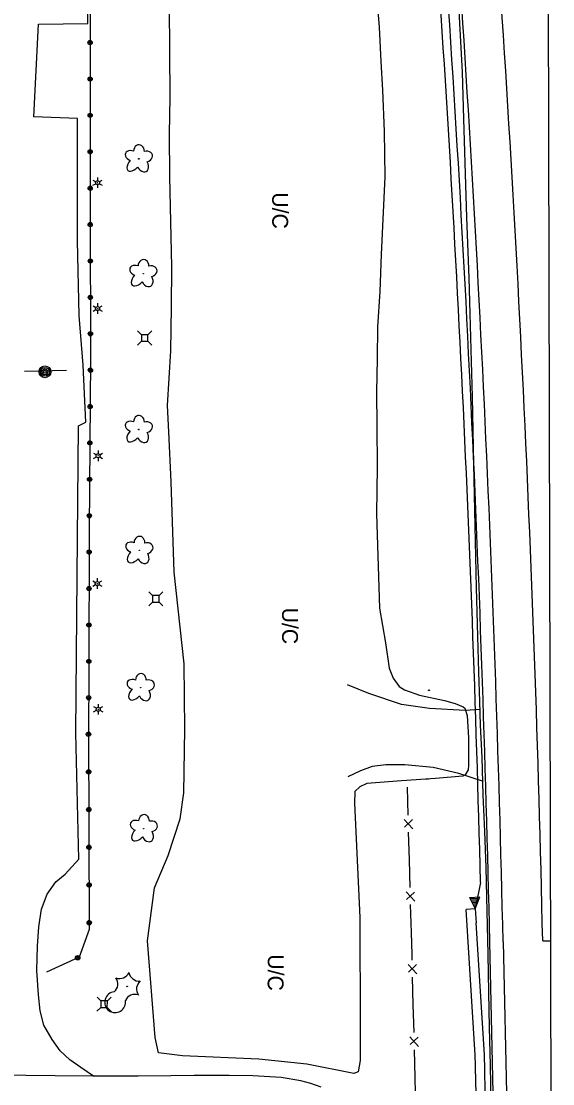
# Model space of a CAD drawing. Extents: x 588843 to 2552415, y 180129 to 269402.
# Drawn here: x 593754.5 to 593955.5, y 184000.1 to 184402 of the extents above; entities that cross this region are included whole.
import ezdxf

# ---------------------------------------------------------------- set-up
doc = ezdxf.new("R2010")
doc.units = 0
for name, color, linetype in [('Default', 7, 'Continuous'), ('E_AREA', 7, 'Continuous'), ('E_AREA_Text', 7, 'Continuous'), ('E_BMGRD_P', 7, 'Continuous'), ('E_DRN', 7, 'Continuous'), ('E_DWY', 7, 'Continuous'), ('E_FEN_P', 7, 'Continuous'), ('E_LAND_Vegetation', 7, 'Continuous'), ('E_LTG', 7, 'Continuous'), ('E_MISCPROP', 7, 'Continuous'), ('E_RDWY_Gravel', 7, 'Continuous'), ('E_SGN', 7, 'Continuous'), ('E_UTL_AG_Bold', 7, 'Continuous'), ('P_BMGRD', 7, 'Continuous'), ('P_RDWY_PavtEdge', 7, 'Continuous'), ('P_RDWY_ShldAgg', 7, 'Continuous'), ('P_RDWY_ShldPaved', 7, 'Continuous')]:
    doc.layers.add(name, color=color, linetype=linetype)

# ---------------------------------------------------------------- blocks, each defined once
blk = doc.blocks.new('CULV2')
at = {"layer": 'E_DRN'}
blk.add_arc((20, 15), 24.6, 216.8699, 323.1301, dxfattribs=at)
blk = doc.blocks.new('UCA')
at = {"layer": 'E_AREA_Text'}
blk.add_text('U/C', height=12, dxfattribs=at).set_placement((-15.33, -6))
blk = doc.blocks.new('DTRE')
at = {"layer": 'Default'}
blk.add_circle((-0.18, 0), 0.183, dxfattribs=at)
for centre, major_axis, ratio in [((-1.87, 5.32), (1.36, -4.98), 0.782863), ((-5.87, 0.15), (4.93, -0.12), 0.832022), ((4.06, 2.74), (-5.27, -2.93), 0.691916), ((-2.49, -5.24), (1.8, 4.86), 0.716896), ((3.54, -3.71), (-5.01, 4.58), 0.560249)]:
    blk.add_ellipse(centre, major_axis=major_axis, ratio=ratio, start_param=1.570796, end_param=4.712389, dxfattribs=at)
blk = doc.blocks.new('PED')
at = {"layer": 'Default'}
for p, q in [((-2.5, 2.5), (-5.33, 5.33)), ((2.5, 2.5), (5.33, 5.33)), ((-2.5, -2.5), (-5.33, -5.33)), ((2.5, -2.5), (5.33, -5.33))]:
    blk.add_line(p, q, dxfattribs=at)
blk.add_lwpolyline([(-2.5, -2.5), (2.5, -2.5), (2.5, 2.5), (-2.5, 2.5)], close=True, dxfattribs=at)
blk = doc.blocks.new('CTRE')
at = {"layer": 'Default'}
blk.add_circle((0, 0), 0.223, dxfattribs=at)
for centre, start, end in [((-11.97, 8.96), 280.2067, 5.97162), ((1.81, 14.92), 220.21132, 305.97623), ((13.83, 5.89), 160.21133, 245.97624), ((-13.83, -5.9), 340.21132, 65.97623), ((-1.81, -14.93), 40.21133, 125.97624), ((12.03, -9.04), 185.92721, 100.25111)]:
    blk.add_arc(centre, 7.87, start, end, dxfattribs=at)
blk = doc.blocks.new('LPOL')
at = {"layer": 'Default'}
for p, q in [((-4, 0), (-1.5, 0)), ((-0.75, 1.3), (-2, 3.46)), ((0.75, 1.3), (2, 3.46)), ((1.5, 0), (4, 0)), ((-2, -3.46), (-0.75, -1.3)), ((2, -3.46), (0.75, -1.3))]:
    blk.add_line(p, q, dxfattribs=at)
for radius in [1.5, 1.5, 1.5, 0.125]:
    blk.add_circle((0, 0), radius, dxfattribs=at)
blk = doc.blocks.new('UCA_1')
at = {"layer": 'E_AREA_Text'}
blk.add_text('U/C', height=12, dxfattribs=at).set_placement((-15.33, -6))
blk = doc.blocks.new('POLE')
at = {"layer": 'Default'}
for radius in [4.46, 3.35, 2.23, 1.12]:
    blk.add_circle((0, 0), radius, dxfattribs=at)

msp = doc.modelspace()

# ---------------------------------------------------------------- linework, layer by layer
at = {"layer": 'E_AREA'}
for points in [[(593816.37, 184134.26), (593816.12, 184158.88), (593812.36, 184193.55), (593811.23, 184227.73), (593810.27, 184246.66), (593809.76, 184256.58), (593811.11, 184277.31), (593811.33, 184293.82), (593811.47, 184309.05), (593810.7, 184343.1), (593810.61, 184359.45), (593810.77, 184373.26), (593810.42, 184425.33)], [(593888.88, 184412.4), (593889.82, 184399.75), (593890.51, 184386.73), (593891.1, 184375.95), (593891.82, 184360.27), (593892, 184343.2), (593890.62, 184313.77), (593890.06, 184299.74), (593889.19, 184286.34), (593889.06, 184274.26), (593888.92, 184261.75), (593889.02, 184248.78), (593889.13, 184233.47), (593888.92, 184215.64), (593889.95, 184179.98), (593892.25, 184166.85), (593893.62, 184157.27), (593895.13, 184153.44), (593897.45, 184150.32), (593899.45, 184149.09), (593905.12, 184147.01), (593914.61, 184145.08), (593918.59, 184143.95), (593921.64, 184142.7), (593922.29, 184142.14), (593923.19, 184139.4), (593923.62, 184130.94)], [(593923.62, 184130.94), (593923.67, 184120.53), (593923.5, 184118.86), (593922.4, 184116.96), (593921.49, 184116.45), (593911.2, 184115.49), (593898.27, 184114.64), (593885.21, 184113.67), (593882.5, 184112.39), (593880.69, 184110.63), (593880.51, 184106.27), (593882.58, 184062.91), (593882.69, 184021.58), (593882.64, 184008.81), (593881.91, 184004.53), (593880.33, 184003.89), (593862.55, 184007.45), (593844.37, 184009.43), (593815.43, 184010.68), (593806.44, 184011.82), (593805.18, 184017.62), (593802.24, 184054.1), (593804.84, 184074.23), (593810.11, 184086.4), (593814.56, 184100.27), (593816.02, 184110.13), (593816.37, 184134.26)]]:
    msp.add_lwpolyline(points, dxfattribs=at)
at = {"layer": 'E_BMGRD_P'}
for points in [[(593780.31, 184463.92), (593780.54, 184391.32), (593780.57, 184330.59), (593780.68, 184274.1), (593780.2, 184209.84), (593780.05, 184155.08), (593779.93, 184133.47)], [(593779.93, 184133.47), (593780.22, 184058.48), (593776.34, 184047.96), (593764, 184042.24)]]:
    msp.add_lwpolyline(points, dxfattribs=at)
for centre, major_axis, ratio in [((593780.54, 184393.93), (0.015, 0.802), 0.996114), ((593780.54, 184393.93), (0.007, 0.404), 0.996114), ((593780.55, 184380.16), (0, 0.802), 0.996116), ((593780.55, 184380.16), (0, 0.404), 0.996116), ((593780.56, 184366.39), (0, 0.802), 0.996116), ((593780.56, 184366.39), (0, 0.404), 0.996116), ((593780.56, 184352.62), (0, 0.802), 0.996116), ((593780.56, 184352.62), (0, 0.404), 0.996116), ((593780.57, 184338.85), (0, 0.802), 0.996116), ((593780.57, 184338.85), (0, 0.404), 0.996116), ((593780.58, 184325.08), (-0.009, 0.802), 0.996116), ((593780.58, 184325.08), (-0.004, 0.404), 0.996116), ((593780.61, 184311.31), (-0.009, 0.802), 0.996116), ((593780.61, 184311.31), (-0.004, 0.404), 0.996116), ((593780.63, 184297.54), (-0.009, 0.802), 0.996116), ((593780.63, 184297.54), (-0.004, 0.404), 0.996116), ((593780.66, 184283.78), (-0.009, 0.802), 0.996116), ((593780.66, 184283.78), (-0.004, 0.404), 0.996116), ((593780.65, 184270.01), (0.006, 0.802), 0.996116), ((593780.65, 184270.01), (0.003, 0.404), 0.996116), ((593780.55, 184256.24), (0.006, 0.802), 0.996116), ((593780.55, 184256.24), (0.003, 0.404), 0.996116), ((593780.44, 184242.47), (0.006, 0.802), 0.996116), ((593780.44, 184242.47), (0.003, 0.404), 0.996116), ((593780.34, 184228.7), (0.006, 0.802), 0.996116), ((593780.34, 184228.7), (0.003, 0.404), 0.996116), ((593780.24, 184214.93), (0.006, 0.802), 0.996116), ((593780.24, 184214.93), (0.003, 0.404), 0.996116), ((593780.18, 184201.16), (-0.002, 0.802), 0.996116), ((593780.18, 184201.16), (-0.001, 0.404), 0.996116), ((593780.14, 184187.39), (-0.002, 0.802), 0.996116), ((593780.14, 184187.39), (-0.001, 0.404), 0.996116), ((593780.1, 184173.62), (-0.002, 0.802), 0.996116), ((593780.1, 184173.62), (-0.001, 0.404), 0.996116), ((593780.06, 184159.86), (-0.002, 0.802), 0.996116), ((593780.06, 184159.86), (-0.001, 0.404), 0.996116), ((593780, 184146.09), (0.004, 0.802), 0.996116), ((593780, 184146.09), (0.002, 0.404), 0.996116), ((593779.93, 184132.28), (0.031, 0.83), 0.99997), ((593779.93, 184132.28), (0.016, 0.418), 0.99997), ((593779.99, 184118.02), (0.031, 0.83), 0.99997), ((593779.99, 184118.02), (0.016, 0.418), 0.99997), ((593780.04, 184103.76), (0.031, 0.83), 0.99997), ((593780.04, 184103.76), (0.016, 0.418), 0.99997), ((593780.1, 184089.51), (0.031, 0.83), 0.99997), ((593780.1, 184089.51), (0.016, 0.418), 0.99997), ((593780.15, 184075.25), (0.031, 0.83), 0.99997), ((593780.15, 184075.25), (0.016, 0.418), 0.99997), ((593780.21, 184060.99), (0.031, 0.83), 0.99997), ((593780.21, 184060.99), (0.016, 0.418), 0.99997), ((593775.86, 184047.73), (0.047, -0.829), 0.999955), ((593775.86, 184047.73), (0.024, -0.418), 0.999955)]:
    msp.add_ellipse(centre, major_axis=major_axis, ratio=ratio, dxfattribs=at)
at = {"layer": 'E_DWY'}
for points in [[(593775.2, 184132.63), (593775.62, 184192.07), (593776.17, 184248.95), (593778.96, 184250.28), (593777.86, 184271.86), (593776.44, 184290.68), (593775.74, 184318.9), (593775.74, 184344.8), (593775.83, 184365.22), (593759.29, 184365.84), (593760.97, 184400.9), (593779.66, 184401.18), (593778.67, 184465.17)], [(593927.92, 184141.58), (593922.46, 184141.21), (593908.91, 184142.07), (593898.27, 184143.52), (593885.96, 184147.75), (593877.85, 184150.91)], [(593781.88, 184002.97), (593777.09, 184006.25), (593772.91, 184009.14), (593769.16, 184012.51), (593766.14, 184016.81), (593763.01, 184022.24), (593761.71, 184027.62), (593761.03, 184033.75), (593760.45, 184042.85), (593760.65, 184052.13), (593761.2, 184059.41), (593762.13, 184066.08), (593764.35, 184071.78), (593767.59, 184076.44), (593771.15, 184079.39), (593776.24, 184085.04), (593775.2, 184132.63)], [(593928.91, 184114.56), (593919.96, 184117.47), (593910.3, 184119.64), (593899.63, 184120.65), (593892.38, 184120.65), (593887.19, 184120.03), (593882.86, 184118.5), (593878.05, 184116.2)]]:
    msp.add_lwpolyline(points, dxfattribs=at)
at = {"layer": 'E_FEN_P'}
for p, q in [((593899.28, 184100.08), (593902.56, 184096.52)), ((593902.46, 184100), (593899.43, 184097.17)), ((593900.05, 184072.65), (593903.32, 184069.09)), ((593903.23, 184072.57), (593900.19, 184069.74)), ((593900.8, 184045.22), (593904.07, 184041.66)), ((593903.98, 184045.14), (593900.94, 184042.31)), ((593901.5, 184017.79), (593904.76, 184014.22)), ((593904.68, 184017.71), (593901.63, 184014.88))]:
    msp.add_line(p, q, dxfattribs=at)
for points in [[(593900.41, 184112.2), (593900.71, 184101.73)], [(593900.89, 184095.25), (593901.18, 184084.77)], [(593901.18, 184084.77), (593901.47, 184074.3)], [(593901.65, 184067.82), (593901.94, 184057.34)], [(593901.94, 184057.34), (593902.17, 184048.98), (593902.23, 184046.87)], [(593902.39, 184040.39), (593902.66, 184029.91)], [(593902.66, 184029.91), (593902.92, 184019.44)], [(593903.09, 184012.96), (593903.35, 184002.48)], [(593903.35, 184002.48), (593903.39, 184001.1), (593903.73, 183992.01)]]:
    msp.add_lwpolyline(points, dxfattribs=at)
at = {"layer": 'E_RDWY_Gravel'}
for points in [[(593919.93, 184408.32), (593920.5, 184396.58), (593921.23, 184382.69), (593921.79, 184365.11), (593922.44, 184344.29), (593922.88, 184327.7), (593923.8, 184304.97), (593924.12, 184291.43), (593924.72, 184273.24), (593925.04, 184259.89), (593925.61, 184234.5), (593925.74, 184222.85), (593926.12, 184205.21), (593926.55, 184187.78), (593926.96, 184173.88), (593927.46, 184155.77), (593927.81, 184144.68), (593928.12, 184135.73)], [(593928.12, 184135.73), (593928.64, 184123.53), (593929.07, 184109.3), (593929.68, 184095.47), (593930.21, 184081.83), (593930.61, 184065.34), (593930.92, 184049.07), (593931.25, 184034.68), (593931.53, 184021.32), (593931.83, 184007.16), (593932.13, 183992.46)], [(593867.87, 183998.74), (593864, 184000.2), (593860.22, 184001.17), (593852.79, 184002.39), (593842.09, 184003.05), (593833.12, 184003.22), (593819.86, 184003.15), (593811.02, 184003.06), (593798.69, 184002.98), (593786.18, 184002.93), (593781.62, 184002.98), (593767.31, 184003.06), (593756.19, 184003.16), (593746.29, 184003.26)]]:
    msp.add_lwpolyline(points, dxfattribs=at)
at = {"layer": 'E_SGN'}
msp.add_lwpolyline([(593755.75, 184269.68), (593771.64, 184269.95)], dxfattribs=at)
at = {"layer": 'P_BMGRD'}
for p, q in [((593923.98, 184070.58), (593927.92, 184070.83)), ((593923.98, 184070.58), (593926.24, 184066.21)), ((593924.23, 184070.09), (593927.74, 184070.32)), ((593924.48, 184069.61), (593927.55, 184069.8)), ((593924.73, 184069.12), (593927.36, 184069.29)), ((593924.99, 184068.64), (593927.18, 184068.77)), ((593925.24, 184068.16), (593926.99, 184068.27)), ((593925.49, 184067.67), (593926.8, 184067.75)), ((593925.74, 184067.18), (593926.61, 184067.24)), ((593926.24, 184066.21), (593927.92, 184070.83)), ((593925.99, 184066.7), (593926.42, 184066.72)), ((593926.24, 184066.21), (593926.57, 184060.95)), ((593929.68, 184011.05), (593926.56, 184060.99)), ((593930.23, 183986.62), (593929.67, 184011.61))]:
    msp.add_line(p, q, dxfattribs=at)
at = {"layer": 'P_RDWY_PavtEdge'}
for p, q in [((593955.52, 183703.01), (593953.77, 184483.94)), ((593926.24, 184066.21), (593922.75, 184065.99)), ((593926.19, 184010.83), (593922.75, 184065.99)), ((593936.73, 184053.8), (593943.41, 183753.81)), ((593954.73, 184053.99), (593951.73, 184053.98)), ((593926.73, 183986.54), (593926.17, 184011.53))]:
    msp.add_line(p, q, dxfattribs=at)
for radius, end in [(8115, 4.312666), (8100, 4.245358)]:
    msp.add_arc((585838.74, 183873.64), radius, 1.274493, end, dxfattribs=at)
at = {"layer": 'P_RDWY_ShldAgg'}
msp.add_line((593928.2, 184076.26), (593926.24, 184066.21), dxfattribs=at)
msp.add_arc((585838.74, 183873.64), 8092, 1.434819, 4.242526, dxfattribs=at)
at = {"layer": 'P_RDWY_ShldPaved'}
msp.add_line((593933.63, 183968.54), (593931.74, 184053.69), dxfattribs=at)
msp.add_arc((585838.74, 183873.64), 8095, 1.274493, 4.242526, dxfattribs=at)

# ---------------------------------------------------------------- block references
at = {"layer": 'E_AREA_Text', "yscale": 0.5}
for name, p, xscale, rotation in [('UCA_1', (593852.42, 184329.62), 0.49999999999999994, -90.03098035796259), ('UCA_1', (593856.14, 184172.52), 0.49999999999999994, -90.03098035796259), ('UCA', (593850.72, 184041.37), 0.5, -90.44645755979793)]:
    msp.add_blockref(name, p, dxfattribs=dict(at, xscale=xscale, rotation=rotation))
at = {"layer": 'E_DRN'}
for p, xscale, yscale, rotation in [((593908.3, 184149.08), 0.020456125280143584, 0.020456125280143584, -0.6460954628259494), ((593908.54, 184115.13), 0.024569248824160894, 0.024569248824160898, 179.7540517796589)]:
    msp.add_blockref('CULV2', p, dxfattribs=dict(at, xscale=xscale, yscale=yscale, rotation=rotation))
at = {"layer": 'E_LAND_Vegetation', "yscale": 0.5}
for name, p, xscale, rotation in [('DTRE', (593798.97, 184349.86), 0.49999999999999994, -90.03098035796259), ('DTRE', (593800.65, 184306.45), 0.49999999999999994, -90.03098035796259), ('DTRE', (593798.96, 184247.47), 0.49999999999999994, -90.03098035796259), ('DTRE', (593799.13, 184201.73), 0.49999999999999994, -90.03098035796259), ('DTRE', (593799.66, 184149.81), 0.49999999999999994, -90.03098035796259), ('DTRE', (593800.8, 184096.48), 0.5, -90.44645755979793), ('CTRE', (593794.57, 184036.89), 0.5, -90.44645755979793)]:
    msp.add_blockref(name, p, dxfattribs=dict(at, xscale=xscale, rotation=rotation))
at = {"layer": 'E_LTG', "xscale": 0.49999999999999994, "yscale": 0.5, "rotation": -90.03098035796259}
for p in [(593783.35, 184340.93), (593783.37, 184293.3), (593783.55, 184237.61), (593783.25, 184189.27), (593783.61, 184141.72)]:
    msp.add_blockref('LPOL', p, dxfattribs=at)
at = {"layer": 'E_MISCPROP', "xscale": 0.49999999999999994, "yscale": 0.5, "rotation": -90.03098035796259}
msp.add_blockref('POLE', (593763.45, 184269.39), dxfattribs=at)
at = {"layer": 'E_UTL_AG_Bold', "yscale": 0.5}
for p, xscale, rotation in [((593801.18, 184282.17), 0.49999999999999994, -90.03098035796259), ((593805.42, 184183.48), 0.49999999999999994, -90.03098035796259), ((593785.81, 184030.14), 0.5, -90.44645755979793)]:
    msp.add_blockref('PED', p, dxfattribs=dict(at, xscale=xscale, rotation=rotation))

doc.saveas('drawing.dxf')
